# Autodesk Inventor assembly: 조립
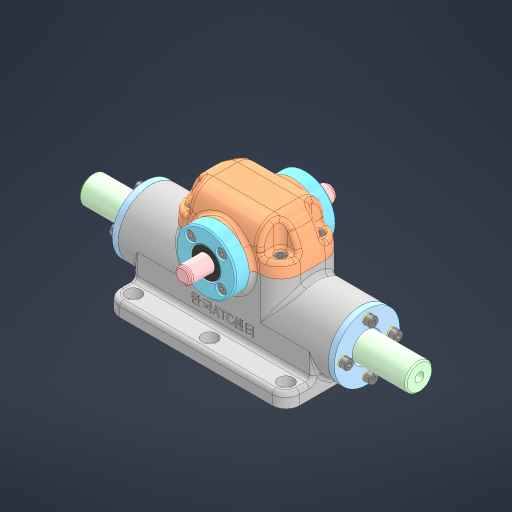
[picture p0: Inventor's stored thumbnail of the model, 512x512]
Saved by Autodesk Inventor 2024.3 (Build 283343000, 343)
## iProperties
Created: 2024-06
Part Number: 조립
Document SubType Name: Assembly
Designer: MyPc
Author: MyPc
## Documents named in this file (13)
- C:\Users\MyPc\Desktop\740604V1019\조립.iam
- C:\Users\MyPc\Desktop\740604V1019\본체.ipt
- C:\Users\MyPc\Desktop\740604V1019\깊은 홈 볼 베어링 6901\깊은 홈 볼 베어링 6901.ipt
- C:\Users\MyPc\Desktop\740604V1019\랙\랙.ipt
- C:\Users\MyPc\Desktop\740604V1019\베어링 커버\베어링 커버.ipt
- C:\Users\MyPc\Desktop\740604V1019\부시 커버\부시 커버.ipt
- C:\Users\MyPc\Desktop\740604V1019\스프링 와셔 M4\스프링 와셔 M4.ipt
- C:\Users\MyPc\Desktop\740604V1019\오일레스 부시\오일레스 부시.ipt
- C:\Users\MyPc\Desktop\740604V1019\오일실 12 22 7\오일실 12 22 7.ipt
- C:\Users\MyPc\Desktop\740604V1019\윗커버\윗커버.ipt
- C:\Users\MyPc\Desktop\740604V1019\육각 소켓 머리 볼트 M4x10\육각 소켓 머리 볼트 M4x10.ipt
- C:\Users\MyPc\Desktop\740604V1019\칼라\칼라.ipt
- C:\Users\MyPc\Desktop\740604V1019\피니언\피니언.ipt
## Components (1 placed, 1 different names)
1. 피니언:1 — 각도:9, 각도:10, 각도:11, 각도:12, 각도:13, 플러쉬:1
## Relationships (6: Angle 5, Flush 1)
- 각도:9 [Angle]: 피니언:1
- 각도:10 [Angle]: 피니언:1
- 각도:11 [Angle]: 피니언:1
- 각도:12 [Angle]: 피니언:1
- 각도:13 [Angle]: 피니언:1
- 플러쉬:1 [Flush]: 피니언:1
